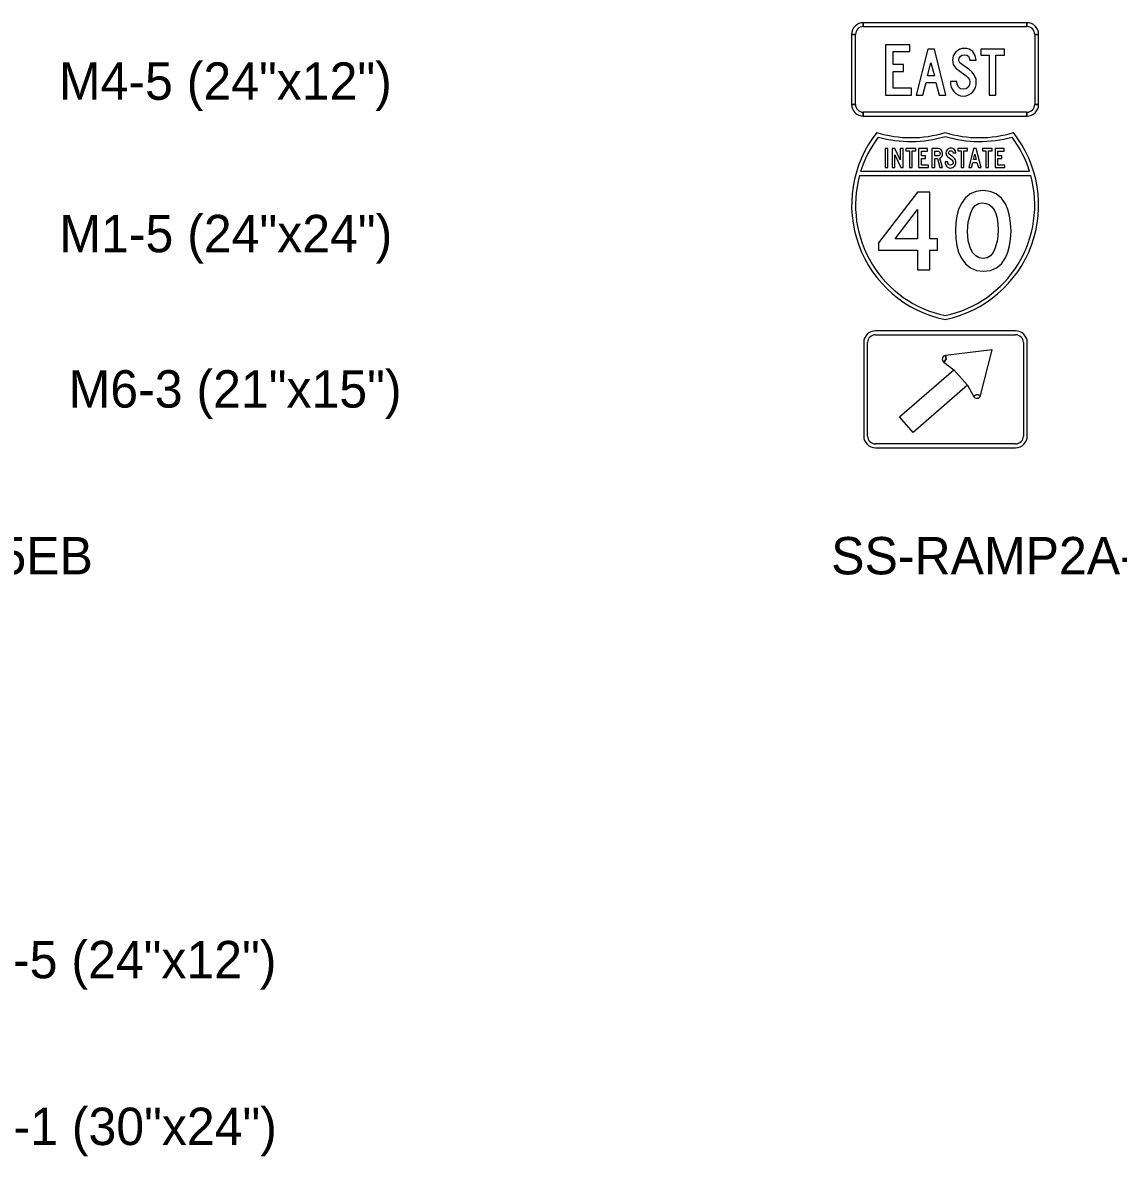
# Model space of a CAD drawing. Extents: x 620856.8 to 620948.6, y 415598.8 to 415658.2.
# Drawn here: x 620887.41 to 620899.13, y 415643.55 to 415655.67 of the extents above; entities that cross this region are included whole.
import ezdxf

# ---------------------------------------------------------------- set-up
doc = ezdxf.new("R2010")
doc.units = 0
doc.layers.add('SIGNS', color=7, linetype='Continuous')

msp = doc.modelspace()

# ---------------------------------------------------------------- linework, layer by layer
at = {"layer": 'SIGNS'}
for p, q in [((620896.401, 415655.631), (620896.401, 415655.673)), ((620898.151, 415655.673), (620898.151, 415655.631)), ((620896.276, 415655.548), (620896.318, 415655.548)), ((620898.235, 415655.548), (620898.276, 415655.548)), ((620896.318, 415654.798), (620896.276, 415654.798)), ((620898.276, 415654.798), (620898.235, 415654.798)), ((620896.401, 415654.673), (620896.401, 415654.715)), ((620898.151, 415654.715), (620898.151, 415654.673)), ((620896.665, 415654.327), (620896.636, 415654.327)), ((620896.636, 415654.327), (620896.636, 415654.122)), ((620896.665, 415654.122), (620896.665, 415654.327)), ((620896.739, 415654.327), (620896.711, 415654.327)), ((620896.711, 415654.327), (620896.711, 415654.122)), ((620896.795, 415654.205), (620896.739, 415654.327)), ((620896.739, 415654.122), (620896.739, 415654.26)), ((620896.739, 415654.26), (620896.803, 415654.122)), ((620896.826, 415654.327), (620896.795, 415654.327)), ((620896.795, 415654.327), (620896.795, 415654.205)), ((620896.826, 415654.122), (620896.826, 415654.327)), ((620896.962, 415654.327), (620896.857, 415654.327)), ((620896.857, 415654.327), (620896.857, 415654.301)), ((620896.857, 415654.301), (620896.894, 415654.301)), ((620896.894, 415654.301), (620896.894, 415654.122)), ((620896.924, 415654.122), (620896.924, 415654.301)), ((620896.924, 415654.301), (620896.962, 415654.301)), ((620896.962, 415654.301), (620896.962, 415654.327)), ((620897.089, 415654.327), (620896.992, 415654.327)), ((620896.992, 415654.327), (620896.992, 415654.122)), ((620897.022, 415654.247), (620897.022, 415654.299)), ((620897.022, 415654.299), (620897.089, 415654.299)), ((620897.065, 415654.247), (620897.022, 415654.247)), ((620897.065, 415654.219), (620897.065, 415654.247)), ((620897.089, 415654.299), (620897.089, 415654.327)), ((620897.288, 415654.298), (620897.285, 415654.278)), ((620897.285, 415654.278), (620897.286, 415654.268)), ((620897.286, 415654.268), (620897.289, 415654.258)), ((620897.3, 415654.315), (620897.288, 415654.298)), ((620897.289, 415654.258), (620897.293, 415654.25)), ((620897.293, 415654.25), (620897.3, 415654.242)), ((620897.308, 415654.322), (620897.3, 415654.315)), ((620897.3, 415654.242), (620897.333, 415654.218)), ((620897.317, 415654.327), (620897.308, 415654.322)), ((620897.313, 415654.279), (620897.315, 415654.288)), ((620897.314, 415654.272), (620897.313, 415654.279)), ((620897.318, 415654.266), (620897.314, 415654.272)), ((620897.315, 415654.288), (620897.32, 415654.296)), ((620897.327, 415654.33), (620897.317, 415654.327)), ((620897.333, 415654.254), (620897.318, 415654.266)), ((620897.32, 415654.296), (620897.328, 415654.301)), ((620897.337, 415654.331), (620897.327, 415654.33)), ((620897.328, 415654.301), (620897.338, 415654.303)), ((620897.357, 415654.238), (620897.333, 415654.254)), ((620897.348, 415654.33), (620897.337, 415654.331)), ((620897.338, 415654.303), (620897.348, 415654.301)), ((620897.358, 415654.327), (620897.348, 415654.33)), ((620897.348, 415654.301), (620897.355, 415654.296)), ((620897.355, 415654.296), (620897.359, 415654.289)), ((620897.372, 415654.225), (620897.357, 415654.238)), ((620897.367, 415654.322), (620897.358, 415654.327)), ((620897.359, 415654.289), (620897.362, 415654.279)), ((620897.362, 415654.279), (620897.391, 415654.279)), ((620897.375, 415654.316), (620897.367, 415654.322)), ((620897.386, 415654.3), (620897.375, 415654.316)), ((620897.391, 415654.279), (620897.386, 415654.3)), ((620897.516, 415654.327), (620897.411, 415654.327)), ((620897.411, 415654.327), (620897.411, 415654.301)), ((620897.411, 415654.301), (620897.448, 415654.301)), ((620897.448, 415654.301), (620897.448, 415654.122)), ((620897.478, 415654.122), (620897.478, 415654.301)), ((620897.478, 415654.301), (620897.516, 415654.301)), ((620897.516, 415654.301), (620897.516, 415654.327)), ((620897.78, 415654.327), (620897.675, 415654.327)), ((620897.675, 415654.327), (620897.675, 415654.301)), ((620897.675, 415654.301), (620897.713, 415654.301)), ((620897.713, 415654.301), (620897.713, 415654.122)), ((620897.742, 415654.122), (620897.742, 415654.301)), ((620897.742, 415654.301), (620897.78, 415654.301)), ((620897.78, 415654.301), (620897.78, 415654.327)), ((620897.908, 415654.327), (620897.811, 415654.327)), ((620897.811, 415654.327), (620897.811, 415654.122)), ((620897.841, 415654.247), (620897.841, 415654.299)), ((620897.841, 415654.299), (620897.908, 415654.299)), ((620897.883, 415654.247), (620897.841, 415654.247)), ((620897.883, 415654.219), (620897.883, 415654.247)), ((620897.908, 415654.299), (620897.908, 415654.327)), ((620896.636, 415654.122), (620896.665, 415654.122)), ((620896.711, 415654.122), (620896.739, 415654.122)), ((620896.803, 415654.122), (620896.826, 415654.122)), ((620896.894, 415654.122), (620896.924, 415654.122)), ((620896.992, 415654.122), (620897.097, 415654.122)), ((620897.022, 415654.15), (620897.022, 415654.219)), ((620897.022, 415654.219), (620897.065, 415654.219)), ((620897.097, 415654.15), (620897.022, 415654.15)), ((620897.097, 415654.122), (620897.097, 415654.15)), ((620897.304, 415654.184), (620897.275, 415654.184)), ((620897.275, 415654.184), (620897.275, 415654.182)), ((620897.275, 415654.182), (620897.276, 415654.17)), ((620897.276, 415654.17), (620897.279, 415654.158)), ((620897.279, 415654.158), (620897.284, 415654.147)), ((620897.284, 415654.147), (620897.291, 415654.138)), ((620897.291, 415654.138), (620897.3, 415654.129)), ((620897.3, 415654.129), (620897.31, 415654.123)), ((620897.305, 415654.17), (620897.304, 415654.184)), ((620897.311, 415654.159), (620897.305, 415654.17)), ((620897.31, 415654.123), (620897.321, 415654.12)), ((620897.321, 415654.151), (620897.311, 415654.159)), ((620897.333, 415654.148), (620897.321, 415654.151)), ((620897.321, 415654.12), (620897.333, 415654.118)), ((620897.333, 415654.218), (620897.346, 415654.209)), ((620897.345, 415654.151), (620897.333, 415654.148)), ((620897.333, 415654.118), (620897.345, 415654.12)), ((620897.355, 415654.158), (620897.345, 415654.151)), ((620897.345, 415654.12), (620897.357, 415654.123)), ((620897.346, 415654.209), (620897.353, 415654.202)), ((620897.353, 415654.202), (620897.36, 415654.191)), ((620897.361, 415654.168), (620897.355, 415654.158)), ((620897.357, 415654.123), (620897.366, 415654.129)), ((620897.36, 415654.191), (620897.363, 415654.181)), ((620897.363, 415654.181), (620897.361, 415654.168)), ((620897.366, 415654.129), (620897.375, 415654.137)), ((620897.38, 415654.215), (620897.372, 415654.225)), ((620897.375, 415654.137), (620897.382, 415654.147)), ((620897.386, 415654.204), (620897.38, 415654.215)), ((620897.382, 415654.147), (620897.387, 415654.157)), ((620897.39, 415654.193), (620897.386, 415654.204)), ((620897.387, 415654.157), (620897.39, 415654.168)), ((620897.391, 415654.181), (620897.39, 415654.193)), ((620897.39, 415654.168), (620897.391, 415654.181)), ((620897.448, 415654.122), (620897.478, 415654.122)), ((620897.713, 415654.122), (620897.742, 415654.122)), ((620897.811, 415654.122), (620897.916, 415654.122)), ((620897.841, 415654.15), (620897.841, 415654.219)), ((620897.841, 415654.219), (620897.883, 415654.219)), ((620897.916, 415654.15), (620897.841, 415654.15)), ((620897.916, 415654.122), (620897.916, 415654.15)), ((620898.18, 415654.081), (620896.373, 415654.081)), ((620898.03, 415652.376), (620896.53, 415652.376)), ((620896.53, 415652.376), (620896.53, 415652.376)), ((620896.53, 415652.334), (620898.03, 415652.334)), ((620896.405, 415652.251), (620896.405, 415651.251)), ((620896.447, 415651.251), (620896.447, 415652.251)), ((620898.114, 415652.251), (620898.114, 415651.251)), ((620898.155, 415651.251), (620898.155, 415652.251)), ((620897.262, 415652.04), (620897.287, 415652.073)), ((620897.287, 415652.073), (620897.28, 415652.114)), ((620897.615, 415651.696), (620897.578, 415651.676)), ((620897.655, 415651.684), (620897.615, 415651.696)), ((620898.03, 415651.167), (620896.53, 415651.167)), ((620896.53, 415651.126), (620898.03, 415651.126)), ((620898.03, 415651.126), (620898.03, 415651.126))]:
    msp.add_line(p, q, dxfattribs=at)
for points in [[(620898.151, 415655.673), (620896.401, 415655.673), (620896.401, 415655.631), (620898.151, 415655.631), (620898.151, 415655.673), (620898.151, 415655.673)], [(620896.276, 415655.548), (620896.276, 415654.798), (620896.318, 415654.798), (620896.318, 415655.548), (620896.276, 415655.548), (620896.276, 415655.548)], [(620898.276, 415654.798), (620898.276, 415655.548), (620898.235, 415655.548), (620898.235, 415654.798), (620898.276, 415654.798), (620898.276, 415654.798)], [(620896.917, 415654.972), (620896.719, 415654.972), (620896.719, 415655.152), (620896.832, 415655.152), (620896.832, 415655.226), (620896.719, 415655.226), (620896.719, 415655.363), (620896.897, 415655.363), (620896.897, 415655.437), (620896.64, 415655.437), (620896.64, 415654.898), (620896.917, 415654.898)], [(620897.333, 415655.045), (620897.333, 415655.041), (620897.335, 415655.011), (620897.342, 415654.983), (620897.354, 415654.958), (620897.371, 415654.935), (620897.392, 415654.914), (620897.416, 415654.9), (620897.442, 415654.891), (620897.472, 415654.888), (620897.501, 415654.891), (620897.527, 415654.9), (620897.551, 415654.914), (620897.572, 415654.933), (620897.588, 415654.956), (620897.6, 415654.981), (620897.607, 415655.008), (620897.61, 415655.038), (620897.607, 415655.067), (620897.599, 415655.094), (620897.585, 415655.119), (620897.566, 415655.143), (620897.529, 415655.175), (620897.472, 415655.214), (620897.434, 415655.243), (620897.426, 415655.257), (620897.423, 415655.273), (620897.428, 415655.295), (620897.441, 415655.314), (620897.46, 415655.326), (620897.483, 415655.33), (620897.507, 415655.326), (620897.525, 415655.315), (620897.534, 415655.298), (620897.541, 415655.273), (620897.61, 415655.273), (620897.599, 415655.323), (620897.573, 415655.363), (620897.553, 415655.378), (620897.532, 415655.389), (620897.507, 415655.396), (620897.481, 415655.398), (620897.456, 415655.396), (620897.433, 415655.389), (620897.411, 415655.377), (620897.392, 415655.36), (620897.364, 415655.319), (620897.355, 415655.271), (620897.357, 415655.247), (620897.364, 415655.224), (620897.376, 415655.203), (620897.393, 415655.184), (620897.472, 415655.127), (620897.502, 415655.105), (620897.52, 415655.088), (620897.536, 415655.064), (620897.542, 415655.037), (620897.537, 415655.008), (620897.523, 415654.984), (620897.5, 415654.966), (620897.472, 415654.96), (620897.442, 415654.966), (620897.418, 415654.987), (620897.405, 415655.013), (620897.401, 415655.045)], [(620897.747, 415654.898), (620897.818, 415654.898), (620897.818, 415655.327), (620897.91, 415655.327), (620897.91, 415655.388), (620897.658, 415655.388), (620897.658, 415655.327), (620897.747, 415655.327)], [(620896.401, 415654.673), (620898.151, 415654.673), (620898.151, 415654.715), (620896.401, 415654.715), (620896.401, 415654.673), (620896.401, 415654.673)], [(620897.781, 415652.172), (620897.28, 415652.114), (620897.287, 415652.073), (620897.262, 415652.04), (620897.371, 415651.96), (620897.515, 415651.795), (620897.578, 415651.676), (620897.615, 415651.696), (620897.655, 415651.684), (620897.781, 415652.172)], [(620896.933, 415651.289), (620896.789, 415651.455), (620897.371, 415651.96), (620897.515, 415651.795), (620896.933, 415651.289)]]:
    msp.add_lwpolyline(points, close=True, dxfattribs=at)
for points in [[(620896.968, 415654.898), (620897.039, 415654.898), (620897.072, 415655.033), (620897.178, 415655.033), (620897.213, 415654.898), (620897.284, 415654.898), (620897.161, 415655.388), (620897.091, 415655.388), (620896.968, 415654.898)], [(620897.089, 415655.103), (620897.124, 415655.245), (620897.161, 415655.103), (620897.089, 415655.103)], [(620896.546, 415654.497), (620896.546, 415654.497)], [(620898.007, 415654.497), (620898.007, 415654.497)], [(620896.561, 415654.449), (620896.561, 415654.449)], [(620897.276, 415654.456), (620897.276, 415654.456)], [(620897.991, 415654.449), (620897.991, 415654.449)], [(620897.166, 415654.122), (620897.166, 415654.22), (620897.193, 415654.22), (620897.22, 415654.122), (620897.249, 415654.122), (620897.219, 415654.223), (620897.232, 415654.23), (620897.242, 415654.242), (620897.247, 415654.255), (620897.249, 415654.27), (620897.248, 415654.282), (620897.246, 415654.293), (620897.241, 415654.302), (620897.235, 415654.311), (620897.227, 415654.318), (620897.218, 415654.323), (620897.207, 415654.326), (620897.195, 415654.327), (620897.134, 415654.327), (620897.134, 415654.122), (620897.166, 415654.122)], [(620897.166, 415654.247), (620897.166, 415654.299), (620897.196, 415654.299), (620897.206, 415654.297), (620897.215, 415654.292), (620897.22, 415654.283), (620897.222, 415654.273), (620897.22, 415654.261), (620897.216, 415654.253), (620897.208, 415654.248), (620897.197, 415654.247), (620897.166, 415654.247)], [(620897.559, 415654.122), (620897.573, 415654.179), (620897.617, 415654.179), (620897.632, 415654.122), (620897.661, 415654.122), (620897.61, 415654.327), (620897.581, 415654.327), (620897.53, 415654.122), (620897.559, 415654.122)], [(620897.58, 415654.208), (620897.595, 415654.267), (620897.61, 415654.208), (620897.58, 415654.208)], [(620896.36, 415654.039), (620896.903, 415654.039), (620897.43, 415654.039), (620898.192, 415654.039)], [(620897.68, 415653.876), (620897.608, 415653.867), (620897.545, 415653.841), (620897.492, 415653.796), (620897.449, 415653.734), (620897.421, 415653.673), (620897.402, 415653.606), (620897.39, 415653.531), (620897.387, 415653.449), (620897.39, 415653.363), (620897.402, 415653.286), (620897.421, 415653.217), (620897.449, 415653.156), (620897.493, 415653.093), (620897.547, 415653.049), (620897.612, 415653.022), (620897.688, 415653.013), (620897.762, 415653.022), (620897.826, 415653.049), (620897.879, 415653.094), (620897.923, 415653.157), (620897.948, 415653.217), (620897.966, 415653.284), (620897.977, 415653.36), (620897.981, 415653.444), (620897.977, 415653.53), (620897.966, 415653.608), (620897.947, 415653.676), (620897.921, 415653.736), (620897.878, 415653.797), (620897.823, 415653.841), (620897.757, 415653.867), (620897.68, 415653.876)], [(620896.981, 415653.03), (620897.114, 415653.03), (620897.114, 415653.238), (620897.193, 415653.238), (620897.193, 415653.359), (620897.114, 415653.359), (620897.114, 415653.86), (620896.981, 415653.86), (620896.565, 415653.317), (620896.565, 415653.238), (620896.981, 415653.238), (620896.981, 415653.03)], [(620896.981, 415653.359), (620896.742, 415653.359), (620896.981, 415653.673), (620896.981, 415653.359)], [(620897.842, 415653.453), (620897.835, 415653.349), (620897.813, 415653.263), (620897.79, 415653.215), (620897.76, 415653.18), (620897.725, 415653.159), (620897.683, 415653.152), (620897.64, 415653.158), (620897.603, 415653.178), (620897.572, 415653.21), (620897.548, 415653.256), (620897.524, 415653.34), (620897.517, 415653.441), (620897.524, 415653.54), (620897.547, 415653.629), (620897.569, 415653.68), (620897.598, 415653.716), (620897.633, 415653.737), (620897.673, 415653.745), (620897.712, 415653.74), (620897.747, 415653.727), (620897.776, 415653.704), (620897.8, 415653.672), (620897.818, 415653.63), (620897.832, 415653.58), (620897.84, 415653.521), (620897.842, 415653.453)], [(620897.276, 415652.539), (620897.276, 415652.539)], [(620897.276, 415652.497), (620897.276, 415652.497)], [(620898.03, 415652.376), (620898.03, 415652.376)], [(620898.155, 415652.251), (620898.155, 415652.251)], [(620896.405, 415651.251), (620896.405, 415651.251)], [(620896.53, 415651.126), (620896.53, 415651.126)]]:
    msp.add_lwpolyline(points, dxfattribs=at)
for centre, radius, start, end in [((620896.401, 415655.548), 0.125, 90.0002, 179.9998), ((620896.401, 415655.548), 0.0833, 90.0002, 179.9998), ((620898.151, 415655.548), 0.125, 0, 90.0002), ((620898.151, 415655.548), 0.0833, 0, 90.0002), ((620896.401, 415654.798), 0.125, 179.9998, 270.0001), ((620896.401, 415654.798), 0.0833, 179.9998, 270.0001), ((620898.151, 415654.798), 0.125, 270.0001, 0.0003), ((620898.151, 415654.798), 0.0833, 270.0001, 0.0003), ((620897.526, 415653.722), 1.25, 141.669, 258.463), ((620896.911, 415655.693), 1.25, 253.009, 286.9909), ((620897.026, 415653.722), 1.25, 281.5371, 38.3311), ((620897.642, 415655.693), 1.25, 253.0091, 286.9911), ((620897.526, 415653.721), 1.208, 142.9959, 162.6952), ((620896.908, 415655.694), 1.292, 254.4391, 286.5746), ((620897.645, 415655.694), 1.292, 253.4255, 285.561), ((620897.027, 415653.721), 1.208, 17.3047, 37.0041), ((620897.526, 415653.721), 1.208, 164.7534, 258.0704), ((620897.027, 415653.721), 1.208, 281.9296, 15.2467), ((620897.027, 415653.721), 1.208, 281.9296126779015, 281.9296393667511), ((620897.526, 415653.721), 1.208, 258.0704, 258.0705), ((620896.53, 415652.251), 0.125, 90, 180), ((620896.53, 415652.251), 0.0833, 89.9998, 180), ((620898.03, 415652.251), 0.125, 0.0002, 89.9998), ((620898.03, 415652.251), 0.0833, 0.0002, 89.9998), ((620897.287, 415652.073), 0.0417, 98.7244, 233.9504), ((620897.615, 415651.696), 0.0417, 208.0499, 343.2759), ((620896.53, 415651.251), 0.125, 180, 269.9999), ((620896.53, 415651.251), 0.0833, 179.9997, 269.9999), ((620898.03, 415651.251), 0.125, 270, 0.0002), ((620898.03, 415651.251), 0.0833, 269.9999, 0.0002)]:
    msp.add_arc(centre, radius, start, end, dxfattribs=at)

# ---------------------------------------------------------------- texts
for s, p in [('M4-5 (24"x12")', (620887.797, 415654.848)), ('M1-5 (24"x24")', (620887.802, 415653.217)), ('M6-3 (21"x15")', (620887.901, 415651.555)), ('SS-ACC-17-STA109+25EB', (620881.635, 415649.771)), ('SS-RAMP2A-17-STA255+85WB', (620896.057, 415649.771)), ('M4-5 (24"x12")', (620886.563, 415645.45)), ('M1-1 (30"x24")', (620886.568, 415643.666))]:
    msp.add_text(s, height=0.4, rotation=0, dxfattribs=at).set_placement(p)

doc.saveas('drawing.dxf')
